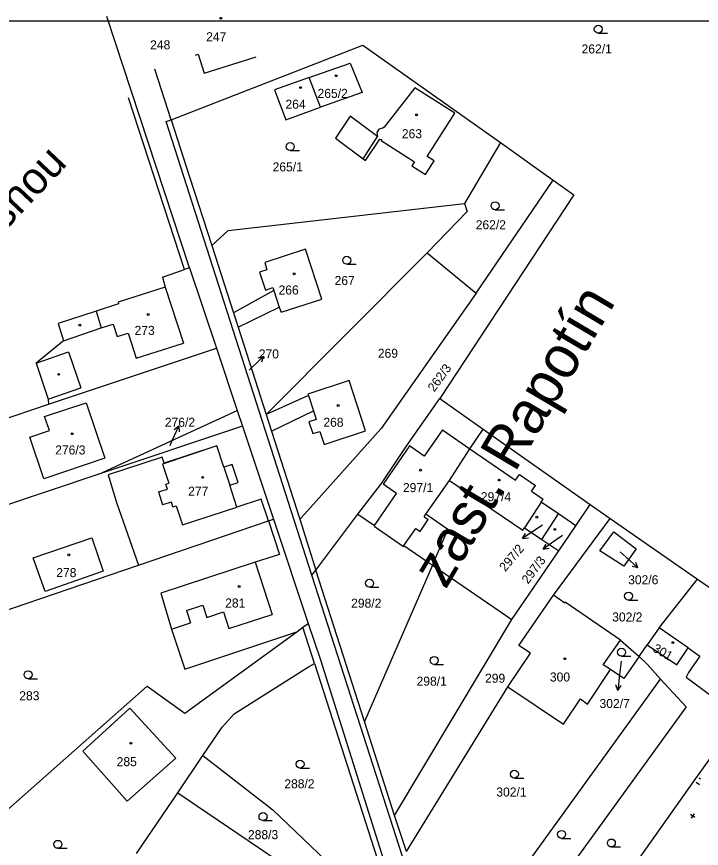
# Model space of a CAD drawing. Extents: x -558358 to -557517, y -1073786 to -1073189.
# Drawn here: x -558227.2 to -558098.4, y -1073345.8 to -1073189.3 of the extents above; entities that cross this region are included whole.
import ezdxf

# ---------------------------------------------------------------- set-up
doc = ezdxf.new("R2010")
doc.units = 0
for name, color, linetype in [('Hranice parcel', 7, 'Continuous'), ('Návěst místo trati', 7, 'Continuous'), ('Parcelní čísla', 7, 'Continuous'), ('Pop  PČ popisy', 7, 'Continuous'), ('Sonda - šrafa - vrstevnice', 7, 'Continuous'), ('Stavba', 7, 'Continuous'), ('Svazek obcí údolí Desné', 7, 'Continuous'), ('Vnitřní kresba', 7, 'Continuous'), ('Vrstva 1', 7, 'Continuous'), ('Značky budov', 7, 'Continuous'), ('Značky kultur', 7, 'Continuous')]:
    doc.layers.add(name, color=color, linetype=linetype)

msp = doc.modelspace()

# ---------------------------------------------------------------- linework, layer by layer
at = {"layer": 'Hranice parcel'}
for p, q in [((-558198.15, -1073208.7), (-558162.11, -1073194.7)), ((-558162.11, -1073194.7), (-558136.18, -1073212.99)), ((-558198.15, -1073208.7), (-558201.24, -1073199.21)), ((-558170.04, -1073206.37), (-558172.21, -1073200.74)), ((-558195.64, -1073236.88), (-558206.21, -1073204.6)), ((-558199.08, -1073209.06), (-558198.15, -1073208.7)), ((-558171.71, -1073294.39), (-558199.08, -1073209.06)), ((-558136.18, -1073212.99), (-558142.95, -1073224.45)), ((-558136.18, -1073212.99), (-558126.3, -1073220.06)), ((-558140.75, -1073241.36), (-558126.3, -1073220.06)), ((-558126.3, -1073220.06), (-558122.4, -1073222.85)), ((-558122.4, -1073222.85), (-558147.61, -1073261.18)), ((-558190.48, -1073232.36), (-558186.42, -1073245.02)), ((-558180.27, -1073264.19), (-558150.02, -1073233.76)), ((-558150.02, -1073233.76), (-558140.75, -1073241.36)), ((-558199.8, -1073238.31), (-558195.64, -1073236.88)), ((-558194.69, -1073236.56), (-558195.64, -1073236.88)), ((-558194.69, -1073236.56), (-558189.64, -1073251.69)), ((-558186.42, -1073245.02), (-558185.55, -1073247.73)), ((-558185.55, -1073247.73), (-558180.27, -1073264.19)), ((-558221.22, -1073262.24), (-558189.64, -1073251.69)), ((-558189.64, -1073251.69), (-558185.73, -1073263.4)), ((-558147.61, -1073261.18), (-558139.47, -1073266.91)), ((-558248.97, -1073271.5), (-558221.22, -1073262.24)), ((-558211.74, -1073275.38), (-558185.73, -1073263.4)), ((-558185.73, -1073263.4), (-558184.74, -1073266.37)), ((-558180.27, -1073264.19), (-558179.28, -1073267.3)), ((-558184.74, -1073266.37), (-558211.74, -1073275.38)), ((-558184.74, -1073266.37), (-558178.92, -1073283.85)), ((-558179.28, -1073267.3), (-558173.98, -1073283.88)), ((-558139.47, -1073266.91), (-558119.31, -1073281.1)), ((-558185.53, -1073276.94), (-558186.65, -1073273.58)), ((-558211.74, -1073275.38), (-558245.1, -1073286.51)), ((-558122.04, -1073285.13), (-558119.31, -1073281.1)), ((-558119.31, -1073281.1), (-558115.55, -1073283.75)), ((-558170.97, -1073293.42), (-558163.02, -1073282.94)), ((-558128.43, -1073287.66), (-558125.31, -1073282.88)), ((-558122.04, -1073285.13), (-558125.31, -1073282.88)), ((-558204.33, -1073292.51), (-558179.86, -1073284.17)), ((-558179.86, -1073284.17), (-558178.92, -1073283.85)), ((-558178.92, -1073283.85), (-558172.36, -1073303.47)), ((-558173.98, -1073283.88), (-558170.97, -1073293.42)), ((-558126.22, -1073298.15), (-558115.55, -1073283.75)), ((-558115.55, -1073283.75), (-558099.14, -1073295.15)), ((-558125.21, -1073289.82), (-558122.04, -1073285.13)), ((-558128.43, -1073287.66), (-558125.21, -1073289.82)), ((-558134.04, -1073302.76), (-558125.21, -1073289.82)), ((-558149, -1073292.52), (-558161.8, -1073321.91)), ((-558149, -1073292.52), (-558134.04, -1073302.76)), ((-558171.71, -1073294.39), (-558170.97, -1073293.42)), ((-558161.8, -1073321.91), (-558170.97, -1073293.42)), ((-558106.35, -1073304.33), (-558099.14, -1073295.15)), ((-558099.14, -1073295.15), (-558082.18, -1073306.93)), ((-558173.36, -1073304.2), (-558172.36, -1073303.47)), ((-558156.12, -1073339.58), (-558134.04, -1073302.76)), ((-558174.53, -1073305.05), (-558173.36, -1073304.2)), ((-558171.18, -1073310.99), (-558173.36, -1073304.2)), ((-558106.35, -1073304.33), (-558108.61, -1073307.47)), ((-558100.91, -1073308.09), (-558106.35, -1073304.33)), ((-558113.61, -1073306.59), (-558110.09, -1073309.68)), ((-558110.09, -1073309.68), (-558108.61, -1073307.47)), ((-558171.18, -1073310.99), (-558158.75, -1073349.79)), ((-558146.53, -1073369.85), (-558106.1, -1073313.94)), ((-558101.25, -1073313.61), (-558091.21, -1073321.1)), ((-558153.86, -1073346.35), (-558134.81, -1073315.38)), ((-558156.12, -1073339.58), (-558161.8, -1073321.91)), ((-558196.91, -1073335.32), (-558192.17, -1073328.33)), ((-558192.17, -1073328.33), (-558179.03, -1073338.54)), ((-558204.65, -1073346.74), (-558196.91, -1073335.32)), ((-558196.91, -1073335.32), (-558167.35, -1073355.36)), ((-558179.03, -1073338.54), (-558163.3, -1073353.56)), ((-558153.86, -1073346.35), (-558156.12, -1073339.58))]:
    msp.add_line(p, q, dxfattribs=at)
for points in [[(-558194.69, -1073236.56), (-558210.23, -1073189.31)], [(-558172.21, -1073200.74), (-558164.51, -1073198.05), (-558162.21, -1073203.59), (-558170.04, -1073206.37)], [(-558172.21, -1073200.74), (-558178.74, -1073203.06), (-558176.58, -1073208.71), (-558170.04, -1073206.37)], [(-558159.35, -1073211.86), (-558164.49, -1073208.05), (-558167.25, -1073212.17), (-558162.05, -1073216.04), (-558161.61, -1073216.37), (-558158.87, -1073212.35), (-558158.54, -1073212.45), (-558158.65, -1073212.62), (-558152.39, -1073216.66), (-558152.86, -1073217.38), (-558150.28, -1073218.99), (-558148.7, -1073216.44), (-558149.97, -1073215.63), (-558144.81, -1073207.5), (-558152.32, -1073202.74), (-558158.11, -1073210.08), (-558158.35, -1073210.31), (-558159.12, -1073210.49), (-558159.48, -1073211.13), (-558159.35, -1073211.86)], [(-558198.15, -1073208.7), (-558194.7, -1073219.45), (-558190.48, -1073232.36)], [(-558190.48, -1073232.36), (-558187.44, -1073229.54), (-558142.95, -1073224.45)], [(-558142.95, -1073224.45), (-558142.49, -1073225.95), (-558150.02, -1073233.76)], [(-558185.55, -1073247.73), (-558177.82, -1073243.95), (-558177.49, -1073244.94), (-558169.79, -1073242.44), (-558172.9, -1073233.07), (-558180.56, -1073235.6), (-558180.13, -1073236.92), (-558181.54, -1073237.39), (-558180.43, -1073240.78), (-558179.03, -1073240.27), (-558178.83, -1073240.86), (-558186.42, -1073245.02)], [(-558199.8, -1073238.31), (-558199.29, -1073240.2), (-558208.14, -1073243.05), (-558208.05, -1073243.33), (-558212.29, -1073244.72), (-558219.4, -1073247.05), (-558218.39, -1073250.28), (-558223.57, -1073254.53), (-558221.27, -1073261.29), (-558221.22, -1073262.24)], [(-558140.75, -1073241.36), (-558158.68, -1073266.81), (-558173.01, -1073282.83), (-558173.98, -1073283.88)], [(-558179.28, -1073267.3), (-558171.41, -1073263.5), (-558170.89, -1073265.11), (-558172.23, -1073265.52), (-558171.5, -1073267.74), (-558170.17, -1073267.35), (-558169.36, -1073269.84), (-558161.57, -1073267.22), (-558164.69, -1073257.79), (-558172.45, -1073260.31), (-558172.35, -1073260.6), (-558180.27, -1073264.19)], [(-558163.02, -1073282.94), (-558158.61, -1073277.12), (-558153.96, -1073270.21), (-558147.61, -1073261.18)], [(-558210.64, -1073272.4), (-558222.13, -1073276.25), (-558224.75, -1073268.45), (-558221.07, -1073267.2), (-558221.97, -1073264.55), (-558214.15, -1073261.94), (-558210.64, -1073272.4)], [(-558149, -1073292.52), (-558146.08, -1073285.8), (-558150.24, -1073282.94), (-558145.79, -1073276.6), (-558141.97, -1073270.62), (-558139.47, -1073266.91)], [(-558186.65, -1073273.58), (-558188.24, -1073274.09), (-558189.55, -1073270.09), (-558199.49, -1073273.33), (-558199.86, -1073272.19), (-558209.99, -1073275.5), (-558208.43, -1073280.69), (-558204.33, -1073292.51)], [(-558179.86, -1073284.17), (-558181.24, -1073280.09), (-558185.8, -1073281.59), (-558187.15, -1073277.46), (-558185.53, -1073276.94)], [(-558125.31, -1073282.88), (-558128.57, -1073280.64), (-558131.66, -1073285.5), (-558128.43, -1073287.66)], [(-558163.02, -1073282.94), (-558159.92, -1073285.05), (-558159.98, -1073285.15), (-558154.48, -1073289), (-558154.38, -1073288.84), (-558149, -1073292.52)], [(-558179.86, -1073284.17), (-558177.8, -1073290.48), (-558182.36, -1073291.97), (-558200.11, -1073297.8), (-558198.12, -1073304.57), (-558195.6, -1073312.09), (-558174.53, -1073305.05)], [(-558114.88, -1073286.21), (-558110.67, -1073289.41), (-558112.99, -1073292.67), (-558117.52, -1073289.79), (-558114.88, -1073286.21)], [(-558210.92, -1073293.66), (-558221.88, -1073297.46), (-558224.1, -1073291.16), (-558213.08, -1073287.38), (-558210.92, -1073293.66)], [(-558247.31, -1073307.29), (-558243.66, -1073305.93), (-558204.33, -1073292.51)], [(-558140.29, -1073392.34), (-558154.66, -1073347.35), (-558171.71, -1073294.39)], [(-558134.81, -1073315.38), (-558130.55, -1073309.06), (-558132.76, -1073307.6), (-558126.22, -1073298.15)], [(-558113.61, -1073306.59), (-558124.02, -1073299.5), (-558124.12, -1073299.64), (-558126.22, -1073298.15)], [(-558172.36, -1073303.47), (-558170.06, -1073310.34), (-558157.85, -1073349.12), (-558143.83, -1073396.83)], [(-558237.16, -1073345.74), (-558202.67, -1073315.29), (-558195.58, -1073320.33), (-558174.53, -1073305.05)], [(-558115.48, -1073312.12), (-558116.87, -1073311.27), (-558113.61, -1073306.59)], [(-558108.61, -1073307.47), (-558103.03, -1073311.24), (-558100.91, -1073308.09)], [(-558100.91, -1073308.09), (-558098.7, -1073309.62), (-558100.86, -1073312.72), (-558101.25, -1073313.61)], [(-558110.09, -1073309.68), (-558113.01, -1073313.83), (-558115.48, -1073312.12)], [(-558106.1, -1073313.94), (-558108.58, -1073311.13), (-558110.09, -1073309.68)], [(-558192.17, -1073328.33), (-558188.55, -1073322.99), (-558186.3, -1073320.49), (-558172.32, -1073311.63), (-558171.18, -1073310.99)], [(-558134.81, -1073315.38), (-558124.37, -1073322.4), (-558121.16, -1073317.67), (-558119.85, -1073318.64), (-558115.48, -1073312.12)], [(-558106.1, -1073313.94), (-558101.27, -1073319.14), (-558143.89, -1073378.07)], [(-558197.27, -1073328.8), (-558205.94, -1073319.43), (-558214.79, -1073327.48), (-558206.42, -1073336.91), (-558197.27, -1073328.8)]]:
    msp.add_lwpolyline(points, dxfattribs=at)
at = {"layer": 'Návěst místo trati'}
for p, q in [((-558099.65, -1073340), (-558100.47, -1073339.44)), ((-558099.77, -1073339.31), (-558100.34, -1073340.13))]:
    msp.add_line(p, q, dxfattribs=at)
at = {"layer": 'Pop  PČ popisy'}
for p, q in [((-558182.95, -1073255.34), (-558180.79, -1073253.26)), ((-558180.79, -1073253.26), (-558181.86, -1073253.59)), ((-558180.79, -1073253.26), (-558181.16, -1073254.31)), ((-558183.46, -1073255.83), (-558182.95, -1073255.34)), ((-558197.94, -1073269.07), (-558196.72, -1073266.33)), ((-558196.72, -1073266.33), (-558197.58, -1073267.04)), ((-558196.72, -1073266.33), (-558196.67, -1073267.45)), ((-558198.36, -1073270.02), (-558197.94, -1073269.07)), ((-558129.56, -1073285.83), (-558132.05, -1073287.51)), ((-558128.29, -1073284.96), (-558129.56, -1073285.83)), ((-558132.05, -1073287.51), (-558131.5, -1073286.53)), ((-558132.05, -1073287.51), (-558130.94, -1073287.36)), ((-558125.73, -1073287.76), (-558128.16, -1073289.52)), ((-558124.56, -1073286.91), (-558125.73, -1073287.76)), ((-558128.16, -1073289.52), (-558127.64, -1073288.53)), ((-558128.16, -1073289.52), (-558127.05, -1073289.34)), ((-558113.72, -1073290), (-558112.59, -1073291.03)), ((-558112.59, -1073291.03), (-558110.36, -1073293.04)), ((-558110.36, -1073293.04), (-558110.77, -1073292)), ((-558110.36, -1073293.04), (-558111.44, -1073292.74)), ((-558113.53, -1073310.57), (-558113.79, -1073313.11)), ((-558113.79, -1073313.11), (-558114.1, -1073316.09)), ((-558114.1, -1073316.09), (-558114.5, -1073315.05)), ((-558114.1, -1073316.09), (-558113.5, -1073315.15))]:
    msp.add_line(p, q, dxfattribs=at)
at = {"layer": 'Sonda - šrafa - vrstevnice'}
for p, q in [((-558098.81, -1073332.53), (-558098.57, -1073332.7)), ((-558099.4, -1073333.34), (-558098.79, -1073333.78))]:
    msp.add_line(p, q, dxfattribs=at)
at = {"layer": 'Svazek obcí údolí Desné'}
msp.add_lwpolyline([(-558091.21, -1073321.1), (-558099.53, -1073332.65), (-558131.71, -1073378.11), (-558132.32, -1073380.12), (-558138.4, -1073389.94), (-558139.67, -1073391.56)], dxfattribs=at)
at = {"layer": 'Vnitřní kresba'}
for p, q in [((-558193.6, -1073196.55), (-558193.1, -1073196.39)), ((-558193.1, -1073196.39), (-558191.93, -1073199.98)), ((-558191.93, -1073199.98), (-558182.14, -1073196.86)), ((-558162.05, -1073216.04), (-558159.35, -1073211.86)), ((-558199.29, -1073240.2), (-558195.85, -1073250.73)), ((-558178.83, -1073240.86), (-558177.82, -1073243.95)), ((-558212.29, -1073244.72), (-558211.3, -1073247.89)), ((-558211.3, -1073247.89), (-558209.09, -1073247.14)), ((-558209.09, -1073247.14), (-558208.34, -1073249.51)), ((-558218.39, -1073250.28), (-558211.3, -1073247.89)), ((-558208.34, -1073249.51), (-558206.26, -1073248.85)), ((-558206.26, -1073248.85), (-558204.74, -1073253.59)), ((-558204.74, -1073253.59), (-558195.85, -1073250.73)), ((-558223.57, -1073254.53), (-558217.44, -1073252.39)), ((-558217.44, -1073252.39), (-558215.14, -1073259.16)), ((-558221.27, -1073261.29), (-558215.14, -1073259.16)), ((-558172.35, -1073260.6), (-558171.41, -1073263.5)), ((-558147.14, -1073267.06), (-558141.97, -1073270.62)), ((-558189.55, -1073270.09), (-558199.78, -1073273.49)), ((-558141.97, -1073270.62), (-558133.4, -1073276.52)), ((-558199.78, -1073273.49), (-558198.6, -1073277.11)), ((-558188.24, -1073274.09), (-558187.15, -1073277.46)), ((-558145.79, -1073276.6), (-558132.02, -1073285.94)), ((-558133.4, -1073276.52), (-558132.65, -1073275.44)), ((-558132.65, -1073275.44), (-558129.62, -1073277.52)), ((-558198.6, -1073277.11), (-558199.14, -1073277.31)), ((-558130.36, -1073278.61), (-558129.62, -1073277.52)), ((-558200.56, -1073278.74), (-558199.78, -1073281.19)), ((-558130.36, -1073278.61), (-558128.2, -1073280.1)), ((-558128.57, -1073280.64), (-558128.2, -1073280.1)), ((-558197.83, -1073281.52), (-558197.23, -1073281.35)), ((-558197.23, -1073281.35), (-558196.05, -1073284.95)), ((-558196.05, -1073284.95), (-558185.8, -1073281.59)), ((-558150.56, -1073283.39), (-558150.24, -1073282.94)), ((-558151.33, -1073286.18), (-558149.78, -1073283.94)), ((-558150.56, -1073283.39), (-558149.78, -1073283.94)), ((-558154.38, -1073288.84), (-558152.12, -1073285.63)), ((-558152.12, -1073285.63), (-558151.33, -1073286.18)), ((-558132.02, -1073285.94), (-558131.66, -1073285.5)), ((-558182.36, -1073291.97), (-558179.17, -1073301.77)), ((-558195.29, -1073301.04), (-558192.22, -1073300.02)), ((-558192.22, -1073300.02), (-558191.45, -1073302.33)), ((-558195.29, -1073301.04), (-558194.51, -1073303.36)), ((-558191.45, -1073302.33), (-558188.34, -1073301.29)), ((-558188.34, -1073301.29), (-558187.3, -1073304.42)), ((-558187.3, -1073304.42), (-558179.17, -1073301.77)), ((-558198.12, -1073304.57), (-558194.51, -1073303.36))]:
    msp.add_line(p, q, dxfattribs=at)
for points in [[(-558147.14, -1073267.06), (-558150.53, -1073272.01), (-558153.32, -1073270.09), (-558158.27, -1073277.3)], [(-558200.56, -1073278.74), (-558198.86, -1073278.21), (-558199.14, -1073277.31)], [(-558159.92, -1073285.05), (-558155.77, -1073279.02), (-558158.27, -1073277.3)], [(-558197.83, -1073281.52), (-558198.09, -1073280.68), (-558199.78, -1073281.19)]]:
    msp.add_lwpolyline(points, dxfattribs=at)
at = {"layer": 'Vrstva 1'}
msp.add_line((-558357.53, -1073190.09), (-557516.53, -1073190.09), dxfattribs=at)
at = {"layer": 'Značky budov'}
for centre in [(-558188.83, -1073189.63), (-558167.13, -1073200.43), (-558173.84, -1073202.67), (-558151.98, -1073207.78), (-558175.02, -1073237.7), (-558202.48, -1073245.34), (-558215.35, -1073247.36), (-558219.32, -1073256.62), (-558166.74, -1073262.46), (-558216.76, -1073267.78), (-558151.26, -1073274.64), (-558192.23, -1073275.99), (-558136.46, -1073276.5), (-558129.37, -1073283.49), (-558125.99, -1073285.78), (-558217.39, -1073290.55), (-558185.37, -1073296.51), (-558103.76, -1073307.08), (-558124.11, -1073310.11), (-558205.73, -1073326.02)]:
    msp.add_circle(centre, 0.175, dxfattribs=at)
at = {"layer": 'Značky kultur'}
for p, q in [((-558117.8, -1073192.42), (-558116.05, -1073192.42)), ((-558175.76, -1073214.51), (-558174.01, -1073214.51)), ((-558137.22, -1073225.64), (-558135.47, -1073225.64)), ((-558165.13, -1073235.9), (-558163.38, -1073235.9)), ((-558160.84, -1073296.66), (-558159.09, -1073296.66)), ((-558112.12, -1073299.08), (-558110.37, -1073299.08)), ((-558113.43, -1073309.64), (-558111.68, -1073309.64)), ((-558148.68, -1073311.18), (-558146.93, -1073311.18)), ((-558225.08, -1073313.87), (-558223.33, -1073313.87)), ((-558173.9, -1073330.7), (-558172.15, -1073330.7)), ((-558133.59, -1073332.58), (-558131.84, -1073332.58)), ((-558180.88, -1073340.55), (-558179.13, -1073340.55)), ((-558124.7, -1073343.92), (-558122.95, -1073343.92)), ((-558219.47, -1073345.78), (-558217.72, -1073345.78)), ((-558115.35, -1073345.53), (-558113.6, -1073345.53))]:
    msp.add_line(p, q, dxfattribs=at)
for centre in [(-558117.8, -1073191.67), (-558175.76, -1073213.76), (-558137.22, -1073224.89), (-558165.13, -1073235.15), (-558160.84, -1073295.91), (-558112.12, -1073298.33), (-558113.43, -1073308.89), (-558148.68, -1073310.43), (-558225.08, -1073313.12), (-558173.9, -1073329.95), (-558133.59, -1073331.83), (-558180.88, -1073339.8), (-558124.7, -1073343.17), (-558115.35, -1073344.78), (-558219.47, -1073345.03)]:
    msp.add_circle(centre, 0.75, dxfattribs=at)

# ---------------------------------------------------------------- texts
at = {"layer": 'Parcelní čísla'}
for s, p in [('247', (-558191.57, -1073193.95)), ('248', (-558202.11, -1073195.47)), ('262/1', (-558120.95, -1073196.24)), ('265/2', (-558170.62, -1073204.6)), ('264', (-558176.65, -1073206.64)), ('263', (-558154.76, -1073212.19)), ('265/1', (-558179.07, -1073218.43)), ('262/2', (-558140.86, -1073229.32)), ('267', (-558167.41, -1073239.81)), ('266', (-558177.95, -1073241.59)), ('273', (-558205.04, -1073249.19)), ('270', (-558181.67, -1073253.61)), ('269', (-558159.28, -1073253.5)), ('276/2', (-558199.35, -1073266.48)), ('268', (-558169.52, -1073266.47)), ('276/3', (-558219.97, -1073271.69)), ('297/1', (-558154.55, -1073278.77)), ('277', (-558194.96, -1073279.44)), ('297/4', (-558139.9, -1073280.48)), ('278', (-558219.77, -1073294.76)), ('302/6', (-558112.19, -1073296.11)), ('281', (-558187.99, -1073300.48)), ('298/2', (-558164.3, -1073300.51)), ('302/2', (-558115.19, -1073303.11)), ('299', (-558139.11, -1073314.63)), ('300', (-558126.91, -1073314.4)), ('298/1', (-558151.99, -1073315.19)), ('283', (-558226.73, -1073317.93)), ('302/7', (-558117.57, -1073319.39)), ('285', (-558208.41, -1073330.33)), ('288/2', (-558176.87, -1073334.49)), ('302/1', (-558136.99, -1073336.04)), ('288/3', (-558183.71, -1073344.06))]:
    msp.add_text(s, height=1.7, dxfattribs=at).set_placement(p)
for s, rotation, p in [('262/3', 54, (-558148.67, -1073260.04)), ('297/2', 50, (-558135.3, -1073293.83)), ('297/3', 53, (-558131.02, -1073296.16)), ('301', 330, (-558107.72, -1073308.64))]:
    msp.add_text(s, height=1.7, rotation=rotation, dxfattribs=at).set_placement(p)
at = {"layer": 'Stavba'}
msp.add_text('zast. Rapotín', height=8, rotation=59.3878, dxfattribs=at).set_placement((-558146.53, -1073297.23))
at = {"layer": 'Vrstva 1'}
msp.add_text('Kouty nad Desnou', height=6, rotation=46.6457, dxfattribs=at).set_placement((-558262.82, -1073265.06))

doc.saveas('drawing.dxf')
